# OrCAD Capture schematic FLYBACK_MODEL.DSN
size A
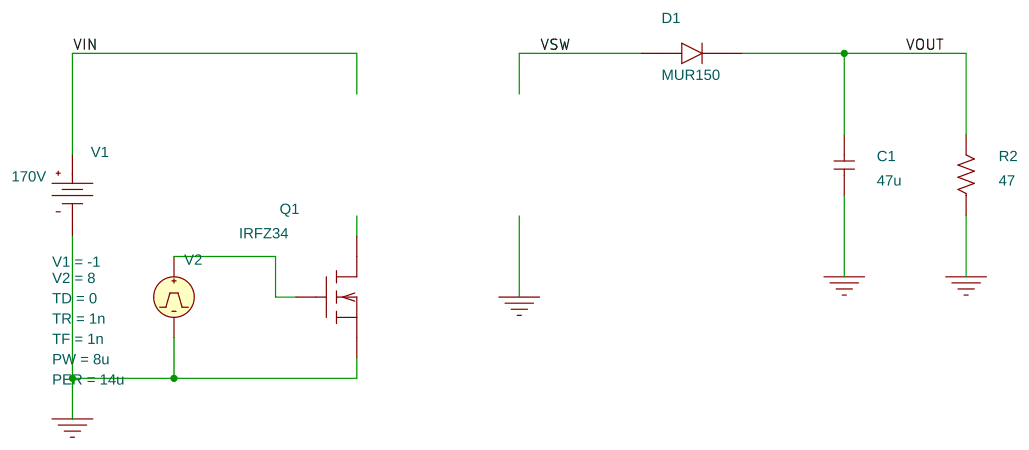
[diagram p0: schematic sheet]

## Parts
C1  47u  [cap196]
D1  MUR150  [dax2do41]
Q1  IRFZ34  [TO220AB]
R2  47  [AXRC05]
V1  VDC
V2  VPULSE

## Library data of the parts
C1 = C
D1 = MUR150
Q1 = IRFZ34
R2 = R
V1 = VDC: DC: 170V
V2 = VPULSE: PER: 14u; PW: 8u; TD: 0; TF: 1n; TR: 1n; V1: -1; V2: 8

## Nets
VIN: V1.0(+)
0: C1.1 Q1.3(s) R2.1 V1.1(-) V2.2(-)
VOUT: C1.2 D1.1(CAT) R2.2
VSW: D1.2(AN)
N00337: Q1.1(g) V2.1(+)

Not connected (* = marked no-connect by the designer): Q1 2(d)
